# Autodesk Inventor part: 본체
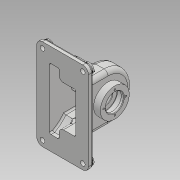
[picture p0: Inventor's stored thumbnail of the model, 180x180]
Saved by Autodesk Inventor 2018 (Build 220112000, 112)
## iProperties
Created: 2024-01
Part Number: 본체
Material: 알루미늄 6061
Document SubType Name: Modeling
Designer: home
Density: 2.7 g/cm^3
Appearance: 기본값
Mass: 914.572 g
Surface Area: 937.064 cm^2
Volume: 338.73 cm^3
Author: home
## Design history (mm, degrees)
sketch "스케치1"
  geometry: L1 (-50, -88)-(50, -88); L2 (50, -88)-(50, 88); L3 (50, 88)-(-50, 88); L4 (-50, 88)-(-50, -88); L5 (-50, -88)-(50, 88); L6 (50, -88)-(-50, 88); 1 further point
  constraints: 12 end point, 2 midpoint, 2 parallel, 1 horizontal, 1 perpendicular
  dimensions: "d0" = 100 distance of L2.end L3.end; "d1" = 176 distance of L1.end L2.end
extrude "돌출1" new body sketch "스케치1" distance "d2" = 9; taper "d3" = 0 deg
node "작업 평면1"
sketch "스케치2"
  geometry: L1 (176, 9)-(176, 0) reference; L2 (176, 0)-(0, 0) reference; L3 (0, 0)-(0, 9) reference; L4 (0, 9)-(176, 9) reference; L5 (42, 9)-(42, 56); L6 (176, 9)-(0, 9) reference; L7 (134, 9)-(134, 56); L8 (134, 9)-(42, 9); A1 r 46 centre (88, 56) between (42, 56) and (134, 56); A2 r 46 centre (88, 56) between (134, 56) and (42, 56); 2 further points
  constraints: 6 end point, 4 point on circle, 2 centre point, 2 point on line, 2 tangent, 1 collinear, 1 midpoint, 1 perpendicular, 1 vertical, 1 vertical alignment
  dimensions: "d5" = 92 diameter of A1; "d6" = 56 distance from line of A1.centre L2
extrude "돌출2" join sketch "스케치2" distance "d7" = 32; taper "d8" = 0 deg
sketch "스케치3"
  geometry: C1 r 28 at (88, 56); A1 r 46 centre (88, 56) between (134, 56) and (42, 56) reference; 1 further point
  constraints: 1 centre point, 1 coincident
  dimensions: "d9" = 56 diameter of C1
extrude "돌출3" join sketch "스케치3" distance "d10" = 13; taper "d11" = 0 deg
sketch "스케치4"
  geometry: L1 (9, -88)-(0, -88) reference; L2 (0, -88)-(0, 88) reference; L3 (0, 88)-(9, 88) reference; L4 (9, 88)-(9, 46) reference; L5 (9, 46)-(9, -46) reference; L6 (9, -46)-(9, -88) reference; L7 (9, 46)-(56, 46) reference; L8 (56, -46)-(9, -46) reference; L9 (0, -67.882)-(0, 67.882); L10 (56, 46)-(9, 46) reference; L11 (56, -46)-(31.39, -46); L12 (9, -46)-(9, 46); L13 (9, 46)-(31.39, 46); L14 (56, 46)-(56, -46); L15 (31.39, -46)-(9, -46); L16 (31.39, 46)-(56, 46); A1 r 46 centre (56, 0) between (56, -46) and (56, 46) reference; A2 r 72 centre (-24, 0) between (0, -67.882) and (31.39, 46); A3 r 72 centre (-24, 0) between (0, 67.882) and (0, -67.882); A4 r 72 centre (-24, 0) between (31.39, 46) and (0, 67.882); 1 further point
  constraints: 14 end point, 8 point on circle, 5 parallel, 3 centre point, 2 horizontal, 2 perpendicular, 2 point on line, 1 horizontal alignment
  dimensions: "d12" = 144 diameter of A2; "d13" = 24 distance from line of L2 A2.centre
  node "절단 모서리 투영2"
extrude "돌출4" join sketch "스케치4" distance "d14" = 32; taper "d15" = 0 deg
sketch "스케치5"
  geometry: L1 (9, -88)-(0, -88) reference; L2 (0, -88)-(0, 88) reference; L3 (0, 88)-(9, 88) reference; L4 (9, 88)-(9, 63.992) reference; L5 (9, 46)-(31.39, 46) reference; L6 (9, 63.992)-(9, 46) reference; L7 (9, -63.992)-(9, -88) reference; L8 (31.39, -46)-(9, -46) reference; L9 (9, -46)-(9, -63.992) reference; L10 (56, -46)-(31.39, -46) reference; L11 (31.39, 46)-(56, 46) reference; C1 r 28 at (56, 0); A1 r 72 centre (-24, 0) between (31.39, 46) and (9, 63.992) reference; A2 r 72 centre (-24, 0) between (9, -63.992) and (31.39, -46) reference; A3 r 72 centre (-24, 0) between (31.39, -46) and (31.39, 46) reference; A4 r 46 centre (56, 0) between (56, -46) and (56, 46) reference; 1 further point
  constraints: 1 centre point, 1 coincident
  dimensions: "d16" = 28 radius of C1
extrude "돌출5" join sketch "스케치5" distance "d17" = 45; taper "d18" = 0 deg
extrude "돌출6" join sketch "스케치4" distance "d19" = 32; taper "d20" = 0 deg
feature "쉘1" dims "d25" = 5
sketch "스케치9"
  geometry: L1 (50, 88)-(50, -88) reference; L2 (50, -88)-(-50, -88) reference; L3 (-50, -88)-(-50, 88) reference; L4 (-50, 88)-(50, 88) reference; L5 (50, 88)-(50, -88) reference; L6 (50, -88)-(-50, -88) reference; L7 (-50, -88)-(-50, 88) reference; L8 (-50, 88)-(50, 88) reference; L9 (-5, -60.869)-(-5, -41) reference; L10 (-27, -60.869)-(-5, -60.869) reference; L11 (-27, 60.869)-(-27, -60.869) reference; L12 (-5, 60.869)-(-27, 60.869) reference; L13 (-5, 41)-(-5, 60.869) reference; L14 (27, 41)-(-5, 41) reference; L15 (27, -41)-(27, 41) reference; L16 (-5, -41)-(27, -41) reference; L17 (45, -83)-(-45, -83) reference; L18 (45, 83)-(45, -83) reference; L19 (-45, 83)-(45, 83) reference; L20 (-45, -83)-(-45, 83) reference; L21 (-6.5, -59.369)-(-6.5, -39.5); L22 (-6.5, -39.5)-(25.5, -39.5); L23 (25.5, -39.5)-(25.5, 39.5); L24 (25.5, 39.5)-(-6.5, 39.5); L25 (-6.5, 39.5)-(-6.5, 59.369); L26 (-6.5, 59.369)-(-25.5, 59.369); L27 (-25.5, 59.369)-(-25.5, -59.369); L28 (-25.5, -59.369)-(-6.5, -59.369); L29 (45, -83)-(45, 83) reference; L30 (45, 83)-(-45, 83) reference; L31 (-45, 83)-(-45, -83) reference; L32 (-45, -83)-(45, -83) reference; L33 (45, -83)-(45, 83) reference; L34 (45, 83)-(-45, 83) reference; L35 (-45, 83)-(-45, -83) reference; L36 (-45, -83)-(45, -83) reference; 1 further point
  constraints: 16 end point, 7 other
  dimensions: "d26" = 1.5 distance between parallel lines of L10 L28
extrude "돌출7" join sketch "스케치9" stored distance "d27" = 32; taper "d28" = 0 deg
sketch "스케치11"
  geometry: L1 (40, 22.131)-(40, 42) reference; L2 (18, 22.131)-(40, 22.131) reference; L3 (18, 143.869)-(18, 22.131) reference; L4 (40, 143.869)-(18, 143.869) reference; L5 (40, 124)-(40, 143.869) reference; L6 (72, 124)-(40, 124) reference; L7 (72, 42)-(72, 124) reference; L8 (40, 42)-(72, 42) reference; L9 (90, 0)-(0, 0) reference; L10 (90, 166)-(90, 0) reference; L11 (0, 166)-(90, 166) reference; L12 (0, 0)-(0, 166) reference; L13 (40, 22.131)-(40, 42) reference; L14 (18, 22.131)-(40, 22.131) reference; L15 (18, 143.869)-(18, 22.131) reference; L16 (40, 143.869)-(18, 143.869) reference; L17 (40, 124)-(40, 143.869) reference; L18 (72, 124)-(40, 124) reference; L19 (72, 42)-(72, 124) reference; L20 (40, 42)-(72, 42) reference; L21 (90, 0)-(0, 0) reference; L22 (90, 166)-(90, 0) reference; L23 (0, 166)-(90, 166) reference; L24 (0, 0)-(0, 166) reference; 1 further point
extrude "돌출8" join sketch "스케치11" distance "d29" = 4; taper "d30" = 0 deg
sketch "스케치13"
  geometry: L1 (-27, 33)-(-27, 79) reference; L2 (-27, 79)-(-40, 79) reference; L3 (-40, 79)-(-40, 33) reference; L4 (-40, 33)-(-27, 33) reference; L5 (40, 33)-(40, 79) reference; L6 (40, 79)-(27, 79) reference; L7 (27, 79)-(27, 33) reference; L8 (27, 33)-(40, 33) reference; L9 (32, 84)-(45, 84) reference; L10 (45, 84)-(45, 28) reference; L11 (45, 28)-(32, 28) reference; L12 (32, 28)-(32, 9) reference; L13 (32, 9)-(50, 9) reference; L14 (50, 9)-(50, 0) reference; L15 (50, 0)-(25.5, 0) reference; L16 (25.5, 0)-(25.5, 97) reference; L17 (25.5, 97)-(5, 97) reference; L18 (5, 97)-(5, 79) reference; L19 (5, 79)-(-25.5, 79) reference; L20 (-25.5, 79)-(-25.5, 0) reference; L21 (-25.5, 0)-(-50, 0) reference; L22 (-50, 0)-(-50, 9) reference; L23 (-50, 9)-(-32, 9) reference; L24 (-32, 9)-(-32, 28) reference; L25 (-32, 28)-(-45, 28) reference; L26 (-45, 28)-(-45, 84) reference; L27 (-45, 84)-(0, 84) reference; L28 (0, 84)-(0, 102) reference; L29 (0, 102)-(32, 102) reference; L30 (32, 102)-(32, 84) reference; L31 (-45, 84)-(-45, 28) reference; L32 (-45, 56)-(45, 56); L33 (-45, 56)-(-45, 73.5); L34 (-45, 73.5)-(-30, 73.5); L35 (-30, 73.5)-(-30, 70.5); L36 (32, 70.126)-(32, 73.5); L37 (32, 84)-(32, 28) reference; L38 (45, 73.5)-(45, 56); L39 (45, 28)-(45, 84) reference; L40 (-30, 70.5)-(30, 70.5); L41 (30, 70.5)-(30, 73.5); L42 (45, 73.5)-(30, 73.5); 1 further point
  constraints: 18 end point, 5 point on line, 2 horizontal, 2 midpoint, 1 collinear, 1 parallel, 1 perpendicular, 1 vertical
  dimensions: "d31" = 35 diameter of L34 L32; "d32" = 29 diameter of L40 L32; "d33" = 15 distance between parallel lines of L33 L35; "d34" = 15 distance between parallel lines of L10 L41
revolve "회전1" sketch "스케치13" stored, may be unused: angle "d35" = 90 deg
fillet "모깎기1" dims "d36" = 11
sketch "스케치15"
  geometry: C1 r 9 at (-39, -77); C2 r 9 at (39, -77); C3 r 9 at (39, 77); C4 r 9 at (-39, 77); A1 r 11 centre (-39, 77) between (-39, 88) and (-50, 77) reference; A2 r 11 centre (-39, -77) between (-50, -77) and (-39, -88) reference; A3 r 11 centre (39, -77) between (39, -88) and (50, -77) reference; A4 r 11 centre (39, 77) between (50, 77) and (39, 88) reference; 1 further point
  constraints: 4 centre point, 4 coincident
  dimensions: "d37" = 9 radius of C1; "d38" = 9 radius of C2; "d39" = 9 radius of C3; "d40" = 9 radius of C4
extrude "돌출9" join sketch "스케치15" distance "d41" = 4; taper "d42" = 0 deg
sketch "스케치16"
  geometry: C1 r 9 at (0, 0) reference; C2 r 9 at (78, 0) reference; C3 r 9 at (78, 154) reference; C4 r 9 at (0, 154) reference; C5 r 9 at (78, 0) reference; 5 further points
  constraints: 4 coincident
hole "구멍1" sketch "스케치16" at (0, 0), (78, 0), (78, 154), (0, 154) diameter "d43" = 9; stored, may be unused: countersink angle "d47" = 90 deg, drill point angle "d49" = 118 deg; dims "d44" = 6, "d45" = 4, "d46" = 2, "d48" = 8
node "작업 평면2"
sketch "스케치17"
  geometry: C1 r 6 at (17, 0); 1 further point
  constraints: 1 centre point, 1 horizontal alignment
  dimensions: "d53" = 12 diameter of C1; "d54" = 17 distance of C1.centre point (0, 0)
extrude "돌출10" join sketch "스케치17" stored distance "d55" = 4; taper "d56" = 0 deg
sketch "스케치18"
  geometry: C1 r 6 at (0, 0) reference; 2 further points
  constraints: 1 coincident
hole "구멍2" sketch "스케치18" at (0, 0) diameter "d57" = 5.188; stored, may be unused: countersink angle "d61" = 90 deg, drill point angle "d63" = 0 deg; dims "d58" = 12, "d59" = 8, "d60" = 2, "d62" = 16
node "작업 평면3"
sketch "스케치19"
  geometry: C1 r 6 at (-17, 0); 1 further point
  constraints: 1 centre point, 1 horizontal alignment
  dimensions: "d65" = 12 diameter of C1; "d66" = 17 distance of point (0, 0) C1.centre
extrude "돌출11" join sketch "스케치19" stored distance "d67" = 4; taper "d68" = 0 deg; dims "d6" = 56, "d9" = 56
sketch "스케치20"
  geometry: C1 r 6 at (0, 0) reference; 2 further points
  constraints: 1 coincident
hole "구멍3" sketch "스케치20" at (0, 0) diameter "d69" = 5.188; stored, may be unused: countersink angle "d73" = 90 deg, drill point angle "d75" = 0 deg; dims "d70" = 12, "d71" = 8, "d72" = 2, "d74" = 16
sketch "스케치21" dims "d76" = 21.5
  geometry: C1 r 17.5 at (0, 0) reference; C2 r 28 at (0, 0) reference; 3 further points
  constraints: 2 vertical alignment, 1 coincident, 2 other
hole "구멍4" sketch "스케치21" at (0, 21.5) diameter "d77" = 3.242; stored, may be unused: countersink angle "d81" = 90 deg, drill point angle "d83" = 118 deg; dims "d78" = 8, "d79" = 8, "d80" = 2, "d82" = 10
node "작업 평면4"
fillet "모깎기4" dims "d89" = 3
fillet "모깎기5" dims "d90" = 8
fillet "모깎기6" dims "d91" = 3
fillet "모깎기7" dims "d92" = 3, "d93" = 0.6
chamfer "모따기1" distance "d94" = 1; stored, may be unused: second distance "d95" = 2, angle "d96" = 45 deg
chamfer "모따기2" distance "d97" = 1; stored, may be unused: second distance "d98" = 2, angle "d99" = 45 deg
fillet "모깎기8" dims "d100" = 7
sketch "스케치22"
  geometry: L1 (-15, -48)-(63, -48) reference; L2 (-26, -42)-(-26, -48) reference; 2 further points
  constraints: 1 other
  dimensions: "d101" = 40 distance from line of L1 point (24, -8); "d102" = 50 distance from line of L2 point (24, -8)
feature "엠보싱1" sketch "스케치22" dims "d8" = 0, "d103" = 0.5, "d104" = 0
fillet "모깎기9" dims "d105" = 3, "d107" = 8
fillet "모깎기10" dims "d106" = 8
fillet "모깎기11" dims "d108" = 3
fillet "모깎기12" dims "d109" = 8
node "솔리드1"
pattern_circular "원형 패턴1" dims angle "d85" = 360 deg
mirror "미러1"
node "투영된 루프1"
node "투영된 루프2"
node "투영된 루프3"
node "투영된 루프4"
node "절단 모서리 투영1"
node "절단 모서리 투영3"
node "절단 모서리 투영6"
node "절단 모서리 투영7"
node "절단 모서리 투영9"
other parameters: "d52" = -106, "d64" = -88, "d87" = -45
